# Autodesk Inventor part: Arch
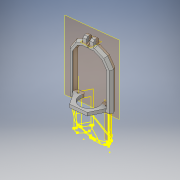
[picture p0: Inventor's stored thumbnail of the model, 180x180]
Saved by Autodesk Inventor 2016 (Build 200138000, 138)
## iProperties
Created: 2015-09
Part Number: Arch
Material: Generic
Document SubType Name: Modeling
Designer: Z
Density: 1 g/cm^3
Appearance: Default
Author: Z
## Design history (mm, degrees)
derived "cane mount.ipt"
  sketch "Sketch37"
    geometry: L1 (7.76, 0)-(8.043, 0) reference; L2 (19.064, 57.15)-(19.064, 0) reference; L3 (15.314, 0)-(15.314, 50.8) reference; L4 (15.314, 50.8)-(8.043, 50.8) reference; L5 (8.043, 0)-(8.043, 50.8) reference; L6 (8.043, 57.15)-(19.064, 57.15) reference; L7 (8.043, 50.8)-(8.043, 57.15) reference; L8 (0, 50.8)-(0, 0) reference; L9 (7.76, 50.8)-(7.76, 0) reference; L10 (7.76, 50.8)-(0, 50.8) reference; L11 (-3.767, 0)-(-3.767, 63.5) reference; L12 (-3.767, 63.5)-(7.76, 63.5) reference; L13 (7.76, 63.5)-(7.76, 50.8) reference; L14 (15.314, 3.175)-(0, 3.175) reference; L15 (0, 3.175)-(0, 15.875) reference; L16 (0, 15.875)-(15.314, 15.875) reference; L17 (15.314, 15.875)-(15.314, 3.175) reference; 5 further points
  sketch "Sketch38"
    geometry: L1 (-12.361, 64.822)-(-4.847, 64.822) reference; L2 (-4.847, 64.822)-(7.871, 9.897) reference; L3 (7.871, 9.897)-(5.044, 0.782) reference; L4 (-56.252, 0.782)-(-58.671, 11.761) reference; L5 (-58.671, 11.761)-(-43.805, 64.822) reference; L6 (-43.805, 64.822)-(-37.173, 64.822) reference; L7 (-40.964, 57.706)-(-42.061, 57.706) reference; L8 (-42.061, 57.706)-(-55.048, 11.353) reference; L9 (-55.048, 11.353)-(-52.719, 0.782) reference; L10 (1.192, 0.782)-(4.181, 10.421) reference; L11 (4.181, 10.421)-(-6.768, 57.706) reference; L12 (-6.768, 57.706)-(-8.569, 57.706) reference; L13 (-24.767, 23.835)-(-24.767, -28.939) reference; C1 r 1.5 at (-24.767, -22.589) reference; 14 further points; 3 other entities
    constraints: 3 other
  sketch "Sketch39"
    geometry: L1 (-25.388, 57.15)-(-14.362, 57.15) reference; L2 (-14.362, 57.15)-(-14.362, 50.8) reference; L3 (-14.362, 50.8)-(-14.362, 0) reference; L4 (-14.362, 0)-(-14.4, 0) reference; L5 (-21.781, 50.8)-(-21.781, 0) reference; L6 (-14.362, 50.8)-(-21.781, 50.8) reference; L7 (-25.388, 0.007)-(-25.388, 57.15) reference; L8 (-14.4, 0)-(-7.597, -10.524) reference; L9 (-7.597, -10.524)-(-14.054, 0) reference; L10 (0, 50.8)-(-14.054, 50.8) reference; L11 (-14.054, 0)-(-14.054, 50.8) reference; L12 (-14.054, 50.8)-(-14.054, 63.5) reference; L13 (-14.054, 63.5)-(3.595, 63.5) reference; L14 (3.595, 63.5)-(3.595, 0.004) reference; L15 (0, 0)-(0, 50.8) reference; L16 (-21.781, 25.4)-(0, 25.4) reference; L17 (0, 25.4)-(0, 6.35) reference; L18 (0, 6.35)-(-21.781, 6.35) reference; L19 (-21.781, 6.35)-(-21.781, 25.4) reference; 3 further points
feature "Solid4::cane mount.ipt" dims "d0" = 10
tag "TaggingFeature1"
workplane "Work Plane6"
workplane "Work Plane7"
workplane "Work Plane14"
workaxis "Work Axis2"
body "Solid1"
